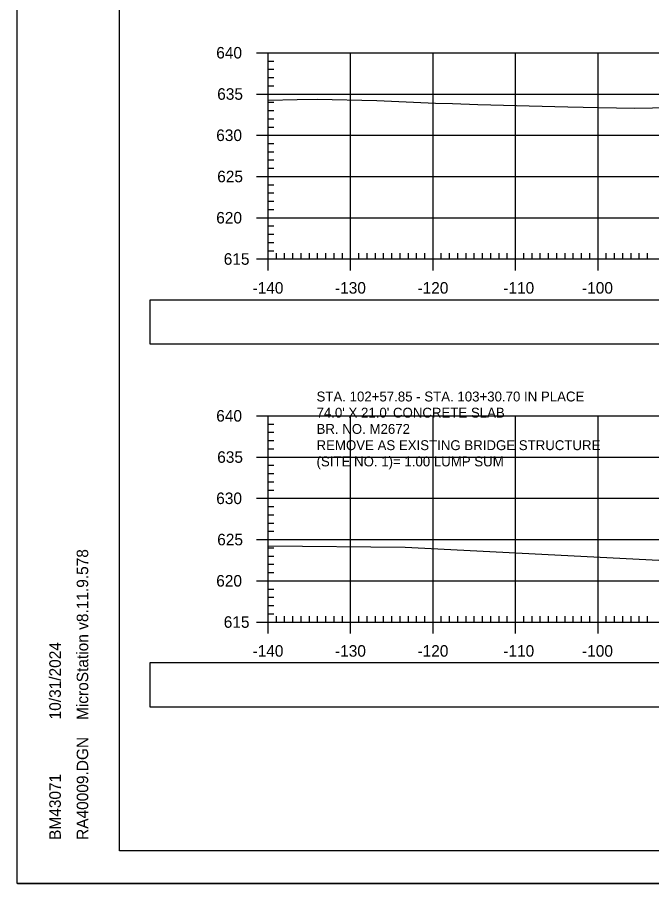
# Model space of a CAD drawing. Extents: x 1381471 to 1382703, y 370300 to 371487.
# Drawn here: x 1381834.4 to 1381911.3, y 370761 to 370866 of the extents above; entities that cross this region are included whole.
import ezdxf

# ---------------------------------------------------------------- set-up
doc = ezdxf.new("R2010")
doc.units = 0
for name, color, linetype in [('Level 18', 7, 'Continuous'), ('Level 22', 7, 'Continuous'), ('Level 26', 7, 'Continuous'), ('Level 4', 7, 'Continuous'), ('Level 5', 7, 'Continuous'), ('Level 6', 7, 'Continuous')]:
    doc.layers.add(name, color=color, linetype=linetype)

msp = doc.modelspace()

# ---------------------------------------------------------------- linework, layer by layer
at = {"layer": 'Level 18'}
for points in [[(1381864.77, 370855.95), (1381868.3, 370856.03), (1381870.7, 370856.07), (1381877.96, 370855.92), (1381885.08, 370855.57), (1381887.13, 370855.52), (1381890.2, 370855.4), (1381901.09, 370855.15), (1381904.83, 370855.06), (1381909.2, 370854.96), (1381924.4, 370855.26), (1381925.2, 370855.23), (1381925.89, 370855.22), (1381942.34, 370854.9), (1381957.17, 370854.46), (1381960.29, 370854.37), (1381963.43, 370854.23), (1381973.52, 370853.93), (1381977.79, 370853.77), (1381979.33, 370853.72), (1381982.17, 370853.92), (1381983.07, 370854.1), (1381986.64, 370854.13), (1381995.44, 370854.32)], [(1381864.77, 370801.92), (1381881.37, 370801.77), (1381912.12, 370800.2), (1381928.24, 370799.82), (1381947.35, 370799.27), (1381988.7, 370799.1)]]:
    msp.add_lwpolyline(points, dxfattribs=at)
at = {"layer": 'Level 22'}
for p, q in [((1381864.77, 370861.69), (1382144.77, 370861.69)), ((1381864.77, 370836.69), (1381864.77, 370861.69)), ((1381874.77, 370836.69), (1381874.77, 370861.69)), ((1381884.77, 370836.69), (1381884.77, 370861.69)), ((1381894.77, 370836.69), (1381894.77, 370861.69)), ((1381904.77, 370836.69), (1381904.77, 370861.69)), ((1381864.77, 370856.69), (1382144.77, 370856.69)), ((1381864.77, 370851.69), (1382144.77, 370851.69)), ((1381864.77, 370846.69), (1382144.77, 370846.69)), ((1381864.77, 370841.69), (1382144.77, 370841.69)), ((1381864.77, 370836.69), (1382144.77, 370836.69)), ((1381864.77, 370817.68), (1382144.77, 370817.68)), ((1381864.77, 370792.68), (1381864.77, 370817.68)), ((1381874.77, 370792.68), (1381874.77, 370817.68)), ((1381884.77, 370792.68), (1381884.77, 370817.68)), ((1381894.77, 370792.68), (1381894.77, 370817.68)), ((1381904.77, 370792.68), (1381904.77, 370817.68)), ((1381864.77, 370812.68), (1382144.77, 370812.68)), ((1381864.77, 370807.68), (1382144.77, 370807.68)), ((1381864.77, 370802.68), (1382144.77, 370802.68)), ((1381864.77, 370797.68), (1382144.77, 370797.68)), ((1381864.77, 370792.68), (1382144.77, 370792.68))]:
    msp.add_line(p, q, dxfattribs=at)
at = {"layer": 'Level 26'}
msp.add_line((1381834.37, 370760.97), (1382167.7, 370760.97), dxfattribs=at)
for points in [[(1381834.36, 370974.3), (1382167.7, 370974.3), (1382167.7, 370760.97), (1381834.36, 370760.97)], [(1382080.69, 370970.41), (1382100.31, 370970.41), (1382100.31, 370960.53), (1382116.42, 370960.53), (1382139.62, 370960.53), (1382139.62, 370927.86), (1382162.83, 370927.86), (1382162.95, 370764.95), (1381846.77, 370764.95), (1381846.77, 370970.41)]]:
    msp.add_lwpolyline(points, close=True, dxfattribs=at)
at = {"layer": 'Level 4'}
for p, q in [((1381863.37, 370861.69), (1381866.17, 370861.69)), ((1381864.77, 370836.69), (1381864.77, 370861.69)), ((1381864.77, 370860.69), (1381865.47, 370860.69)), ((1381864.77, 370859.69), (1381865.47, 370859.69)), ((1381864.77, 370858.69), (1381865.47, 370858.69)), ((1381864.77, 370857.69), (1381865.47, 370857.69)), ((1381863.37, 370856.69), (1381866.17, 370856.69)), ((1381864.77, 370855.69), (1381865.47, 370855.69)), ((1381864.77, 370854.69), (1381865.47, 370854.69)), ((1381864.77, 370853.69), (1381865.47, 370853.69)), ((1381864.77, 370852.69), (1381865.47, 370852.69)), ((1381863.37, 370851.69), (1381866.17, 370851.69)), ((1381864.77, 370850.69), (1381865.47, 370850.69)), ((1381864.77, 370849.69), (1381865.47, 370849.69)), ((1381864.77, 370848.69), (1381865.47, 370848.69)), ((1381864.77, 370847.69), (1381865.47, 370847.69)), ((1381863.37, 370846.69), (1381866.17, 370846.69)), ((1381864.77, 370845.69), (1381865.47, 370845.69)), ((1381864.77, 370844.69), (1381865.47, 370844.69)), ((1381864.77, 370843.69), (1381865.47, 370843.69)), ((1381864.77, 370842.69), (1381865.47, 370842.69)), ((1381863.37, 370841.69), (1381866.17, 370841.69)), ((1381864.77, 370840.69), (1381865.47, 370840.69)), ((1381864.77, 370839.69), (1381865.47, 370839.69)), ((1381864.77, 370838.69), (1381865.47, 370838.69)), ((1381864.77, 370835.29), (1381864.77, 370838.09)), ((1381864.77, 370837.69), (1381865.47, 370837.69)), ((1381874.77, 370835.29), (1381874.77, 370838.09)), ((1381884.77, 370835.29), (1381884.77, 370838.09)), ((1381894.77, 370835.29), (1381894.77, 370838.09)), ((1381904.77, 370835.29), (1381904.77, 370838.09)), ((1381863.37, 370836.69), (1381866.17, 370836.69)), ((1381864.77, 370836.69), (1382144.77, 370836.69)), ((1381865.77, 370836.69), (1381865.77, 370837.39)), ((1381866.77, 370836.69), (1381866.77, 370837.39)), ((1381867.77, 370836.69), (1381867.77, 370837.39)), ((1381868.77, 370836.69), (1381868.77, 370837.39)), ((1381869.77, 370836.69), (1381869.77, 370837.39)), ((1381870.77, 370836.69), (1381870.77, 370837.39)), ((1381871.77, 370836.69), (1381871.77, 370837.39)), ((1381872.77, 370836.69), (1381872.77, 370837.39)), ((1381873.77, 370836.69), (1381873.77, 370837.39)), ((1381875.77, 370836.69), (1381875.77, 370837.39)), ((1381876.77, 370836.69), (1381876.77, 370837.39)), ((1381877.77, 370836.69), (1381877.77, 370837.39)), ((1381878.77, 370836.69), (1381878.77, 370837.39)), ((1381879.77, 370836.69), (1381879.77, 370837.39)), ((1381880.77, 370836.69), (1381880.77, 370837.39)), ((1381881.77, 370836.69), (1381881.77, 370837.39)), ((1381882.77, 370836.69), (1381882.77, 370837.39)), ((1381883.77, 370836.69), (1381883.77, 370837.39)), ((1381885.77, 370836.69), (1381885.77, 370837.39)), ((1381886.77, 370836.69), (1381886.77, 370837.39)), ((1381887.77, 370836.69), (1381887.77, 370837.39)), ((1381888.77, 370836.69), (1381888.77, 370837.39)), ((1381889.77, 370836.69), (1381889.77, 370837.39)), ((1381890.77, 370836.69), (1381890.77, 370837.39)), ((1381891.77, 370836.69), (1381891.77, 370837.39)), ((1381892.77, 370836.69), (1381892.77, 370837.39)), ((1381893.77, 370836.69), (1381893.77, 370837.39)), ((1381895.77, 370836.69), (1381895.77, 370837.39)), ((1381896.77, 370836.69), (1381896.77, 370837.39)), ((1381897.77, 370836.69), (1381897.77, 370837.39)), ((1381898.77, 370836.69), (1381898.77, 370837.39)), ((1381899.77, 370836.69), (1381899.77, 370837.39)), ((1381900.77, 370836.69), (1381900.77, 370837.39)), ((1381901.77, 370836.69), (1381901.77, 370837.39)), ((1381902.77, 370836.69), (1381902.77, 370837.39)), ((1381903.77, 370836.69), (1381903.77, 370837.39)), ((1381905.77, 370836.69), (1381905.77, 370837.39)), ((1381906.77, 370836.69), (1381906.77, 370837.39)), ((1381907.77, 370836.69), (1381907.77, 370837.39)), ((1381908.77, 370836.69), (1381908.77, 370837.39)), ((1381909.77, 370836.69), (1381909.77, 370837.39)), ((1381910.77, 370836.69), (1381910.77, 370837.39)), ((1381863.37, 370817.68), (1381866.17, 370817.68)), ((1381864.77, 370792.68), (1381864.77, 370817.68)), ((1381864.77, 370816.68), (1381865.47, 370816.68)), ((1381864.77, 370815.68), (1381865.47, 370815.68)), ((1381864.77, 370814.68), (1381865.47, 370814.68)), ((1381864.77, 370813.68), (1381865.47, 370813.68)), ((1381863.37, 370812.68), (1381866.17, 370812.68)), ((1381864.77, 370811.68), (1381865.47, 370811.68)), ((1381864.77, 370810.68), (1381865.47, 370810.68)), ((1381864.77, 370809.68), (1381865.47, 370809.68)), ((1381864.77, 370808.68), (1381865.47, 370808.68)), ((1381863.37, 370807.68), (1381866.17, 370807.68)), ((1381864.77, 370806.68), (1381865.47, 370806.68)), ((1381864.77, 370805.68), (1381865.47, 370805.68)), ((1381864.77, 370804.68), (1381865.47, 370804.68)), ((1381864.77, 370803.68), (1381865.47, 370803.68)), ((1381863.37, 370802.68), (1381866.17, 370802.68)), ((1381864.77, 370801.68), (1381865.47, 370801.68)), ((1381864.77, 370800.68), (1381865.47, 370800.68)), ((1381864.77, 370799.68), (1381865.47, 370799.68)), ((1381864.77, 370798.68), (1381865.47, 370798.68)), ((1381863.37, 370797.68), (1381866.17, 370797.68)), ((1381864.77, 370796.68), (1381865.47, 370796.68)), ((1381864.77, 370795.68), (1381865.47, 370795.68)), ((1381864.77, 370794.68), (1381865.47, 370794.68)), ((1381864.77, 370791.28), (1381864.77, 370794.08)), ((1381864.77, 370793.68), (1381865.47, 370793.68)), ((1381874.77, 370791.28), (1381874.77, 370794.08)), ((1381884.77, 370791.28), (1381884.77, 370794.08)), ((1381894.77, 370791.28), (1381894.77, 370794.08)), ((1381904.77, 370791.28), (1381904.77, 370794.08)), ((1381863.37, 370792.68), (1381866.17, 370792.68)), ((1381864.77, 370792.68), (1382144.77, 370792.68)), ((1381865.77, 370792.68), (1381865.77, 370793.38)), ((1381866.77, 370792.68), (1381866.77, 370793.38)), ((1381867.77, 370792.68), (1381867.77, 370793.38)), ((1381868.77, 370792.68), (1381868.77, 370793.38)), ((1381869.77, 370792.68), (1381869.77, 370793.38)), ((1381870.77, 370792.68), (1381870.77, 370793.38)), ((1381871.77, 370792.68), (1381871.77, 370793.38)), ((1381872.77, 370792.68), (1381872.77, 370793.38)), ((1381873.77, 370792.68), (1381873.77, 370793.38)), ((1381875.77, 370792.68), (1381875.77, 370793.38)), ((1381876.77, 370792.68), (1381876.77, 370793.38)), ((1381877.77, 370792.68), (1381877.77, 370793.38)), ((1381878.77, 370792.68), (1381878.77, 370793.38)), ((1381879.77, 370792.68), (1381879.77, 370793.38)), ((1381880.77, 370792.68), (1381880.77, 370793.38)), ((1381881.77, 370792.68), (1381881.77, 370793.38)), ((1381882.77, 370792.68), (1381882.77, 370793.38)), ((1381883.77, 370792.68), (1381883.77, 370793.38)), ((1381885.77, 370792.68), (1381885.77, 370793.38)), ((1381886.77, 370792.68), (1381886.77, 370793.38)), ((1381887.77, 370792.68), (1381887.77, 370793.38)), ((1381888.77, 370792.68), (1381888.77, 370793.38)), ((1381889.77, 370792.68), (1381889.77, 370793.38)), ((1381890.77, 370792.68), (1381890.77, 370793.38)), ((1381891.77, 370792.68), (1381891.77, 370793.38)), ((1381892.77, 370792.68), (1381892.77, 370793.38)), ((1381893.77, 370792.68), (1381893.77, 370793.38)), ((1381895.77, 370792.68), (1381895.77, 370793.38)), ((1381896.77, 370792.68), (1381896.77, 370793.38)), ((1381897.77, 370792.68), (1381897.77, 370793.38)), ((1381898.77, 370792.68), (1381898.77, 370793.38)), ((1381899.77, 370792.68), (1381899.77, 370793.38)), ((1381900.77, 370792.68), (1381900.77, 370793.38)), ((1381901.77, 370792.68), (1381901.77, 370793.38)), ((1381902.77, 370792.68), (1381902.77, 370793.38)), ((1381903.77, 370792.68), (1381903.77, 370793.38)), ((1381905.77, 370792.68), (1381905.77, 370793.38)), ((1381906.77, 370792.68), (1381906.77, 370793.38)), ((1381907.77, 370792.68), (1381907.77, 370793.38)), ((1381908.77, 370792.68), (1381908.77, 370793.38)), ((1381909.77, 370792.68), (1381909.77, 370793.38)), ((1381910.77, 370792.68), (1381910.77, 370793.38))]:
    msp.add_line(p, q, dxfattribs=at)
at = {"layer": 'Level 6'}
for p, q in [((1381846.77, 370764.95), (1381846.77, 370970.41)), ((1381846.77, 370764.95), (1381846.77, 370764.95)), ((1382162.95, 370764.95), (1381846.77, 370764.95))]:
    msp.add_line(p, q, dxfattribs=at)
for points in [[(1381850.41, 370826.39), (1382159.14, 370826.39), (1382159.14, 370831.71), (1381850.41, 370831.71)], [(1381850.41, 370782.42), (1382159.14, 370782.42), (1382159.14, 370787.74), (1381850.41, 370787.74)]]:
    msp.add_lwpolyline(points, close=True, dxfattribs=at)

# ---------------------------------------------------------------- texts
at = {"layer": 'Level 5'}
for s, height, p in [('640', 1.4, (1381858.48, 370860.99)), ('635', 1.4, (1381858.6, 370855.99)), ('630', 1.4, (1381858.48, 370850.99)), ('625', 1.4, (1381858.6, 370845.99)), ('620', 1.4, (1381858.48, 370840.99)), ('615', 1.4, (1381859.39, 370835.99)), ('-140', 1.4, (1381862.88, 370832.49)), ('-130', 1.4, (1381872.88, 370832.49)), ('-120', 1.4, (1381882.88, 370832.49)), ('-110', 1.4, (1381893.28, 370832.49)), ('-100', 1.4, (1381902.83, 370832.49)), ('STA. 102+57.85 - STA. 103+30.70 IN PLACE', 1.2, (1381870.64, 370819.42)), ("74.0' X 21.0' CONCRETE SLAB", 1.2, (1381870.64, 370817.46)), ('640', 1.4, (1381858.48, 370816.98)), ('BR. NO. M2672', 1.2, (1381870.64, 370815.49)), ('REMOVE AS EXISTING BRIDGE STRUCTURE ', 1.2, (1381870.64, 370813.52)), ('635', 1.4, (1381858.6, 370811.98)), ('(SITE NO. 1)= 1.00 LUMP SUM', 1.2, (1381870.64, 370811.55)), ('630', 1.4, (1381858.48, 370806.98)), ('625', 1.4, (1381858.6, 370801.98)), ('620', 1.4, (1381858.48, 370796.98)), ('615', 1.4, (1381859.39, 370791.98)), ('-140', 1.4, (1381862.88, 370788.48)), ('-130', 1.4, (1381872.88, 370788.48)), ('-120', 1.4, (1381882.88, 370788.48)), ('-110', 1.4, (1381893.28, 370788.48)), ('-100', 1.4, (1381902.83, 370788.48))]:
    msp.add_text(s, height=height, dxfattribs=at).set_placement(p)
at = {"layer": 'Level 6'}
for s, p in [('MicroStation v8.11.9.578', (1381842.96, 370780.81)), ('10/31/2024', (1381839.64, 370780.88)), ('RA40009.DGN', (1381842.96, 370766.27)), ('BM43071', (1381839.64, 370766.27))]:
    msp.add_text(s, height=1.4, rotation=90, dxfattribs=at).set_placement(p)

doc.saveas('drawing.dxf')
